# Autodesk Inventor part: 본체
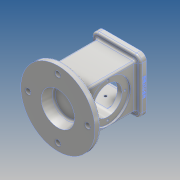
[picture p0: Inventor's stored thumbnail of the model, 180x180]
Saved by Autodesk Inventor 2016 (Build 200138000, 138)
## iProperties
Created: 2018-10
Part Number: 본체
Material: 알루미늄 6061
Document SubType Name: Modeling
Designer: Administrator
Density: 2.7 g/cm^3
Appearance: 알루미늄 - 평지
Mass: 1090.69 g
Surface Area: 720.185 cm^2
Volume: 403.96 cm^3
Author: Administrator
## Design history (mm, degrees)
sketch "스케치1"
  geometry: C1 r 62.5 at (0, 0); 1 further point
  constraints: 1 centre point, 1 coincident
  dimensions: "d0" = 125 diameter of C1
extrude "돌출1" new body sketch "스케치1" distance "d1" = 10; taper "d2" = 0 deg
sketch "스케치2"
  geometry: L1 (33, 37)-(-33, 37); L2 (-33, 37)-(-33, -37); L3 (-33, -37)-(33, -37); L4 (33, -37)-(33, 37); L5 (33, 37)-(-33, -37); L6 (-33, 37)-(33, -37); C1 r 62.5 at (0, 0) reference
  constraints: 12 end point, 2 midpoint, 2 parallel, 1 horizontal, 1 perpendicular
  dimensions: "d3" = 66 distance of L3.end L2.end; "d4" = 74 distance of L2.end L1.end
extrude "돌출2" join sketch "스케치2" distance "d5" = 88; taper "d6" = 0 deg
sketch "스케치3"
  geometry: L1 (41, 46)-(-41, 46); L2 (-41, 46)-(-41, -46); L3 (-41, -46)-(41, -46); L4 (41, -46)-(41, 46); L5 (41, 46)-(-41, -46); L6 (-41, 46)-(41, -46); 1 further point
  constraints: 12 end point, 2 midpoint, 2 parallel, 1 horizontal, 1 perpendicular
  dimensions: "d7" = 82 distance of L3.end L2.end; "d8" = 92 distance of L2.end L1.end
extrude "돌출3" join sketch "스케치3" distance "d9" = 10; taper "d10" = 0 deg
fillet "모깎기1" dims "d11" = 3
fillet "모깎기2" dims "d12" = 10
sketch "스케치4"
  geometry: C1 r 59.5 at (0, 0) reference; 4 further points
  constraints: 2 horizontal alignment, 2 vertical alignment
  dimensions: "d13" = 100 distance of point (0, 50) point (0, -50); "d14" = 100 distance of point (-50, 0) point (50, 0); "d15" = 50 horizontal distance of point (-50, 0) point (0, -50); "d16" = 50 horizontal distance of point (0, 50) point (50, 0)
hole "구멍1" sketch "스케치4" at (0, -50), (0, 50), (-50, 0), (50, 0) diameter "d17" = 9; stored, may be unused: countersink angle "d21" = 90 deg, drill point angle "d23" = 0 deg; dims "d18" = 6, "d19" = 4, "d20" = 2, "d22" = 8
sketch "스케치6"
  geometry: L1 (-33, 13)-(-33, 95) reference; L2 (-33, 54)-(33, 54); L3 (33, 95)-(33, 13) reference; L4 (-33, 54)-(-33, 89); L5 (-33, 89)-(-30, 89); L6 (-30, 89)-(-30, 78); L7 (-30, 78)-(30, 78); L8 (30, 78)-(30, 89); L9 (30, 89)-(33, 89); L10 (33, 89)-(33, 54); 1 further point
  constraints: 16 end point, 4 point on line, 3 perpendicular, 2 collinear, 2 midpoint, 1 horizontal
  dimensions: "d24" = 70 diameter of L5 L2; "d25" = 48 diameter of L7 L2; "d26" = 3 distance between parallel lines of L1 L6
revolve "회전1" sketch "스케치6" stored, may be unused: angle "d27" = 90 deg
sketch "스케치7"
  geometry: C1 r 35 at (0, 0) reference; C2 r 24 at (0, 0) reference; A1 r 29 centre (0, 0) between (0, 29) and (-29, 0); 3 further points
  constraints: 4 point on circle, 2 horizontal alignment, 2 vertical alignment, 1 centre point, 1 coincident
  dimensions: "d28" = 58 diameter of A1
hole "구멍2" sketch "스케치7" at (0, 29), (-29, 0), (0, -29), (29, 0) diameter "d29" = 3.242; stored, may be unused: countersink angle "d33" = 90 deg, drill point angle "d35" = 118 deg; dims "d30" = 4, "d31" = 4, "d32" = 2, "d34" = 6
sketch "스케치8"
  geometry: L1 (-26, -26)-(26, -26); L2 (26, -26)-(26, 26); L3 (26, 26)-(-26, 26); L4 (-26, 26)-(-26, -26); L5 (-26, -26)-(26, 26); L6 (26, -26)-(-26, 26); 1 further point
  constraints: 12 end point, 2 midpoint, 2 parallel, 1 horizontal, 1 perpendicular
  dimensions: "d36" = 52 distance of L3.end L2.end; "d37" = 52 distance of L2.end L1.end
extrude "돌출4" cut sketch "스케치8" distance "d38" = 8; taper "d39" = 0 deg
sketch "스케치9"
  geometry: L1 (-22, -22)-(22, -22); L2 (22, -22)-(22, 22); L3 (22, 22)-(-22, 22); L4 (-22, 22)-(-22, -22); L5 (-22, -22)-(22, 22); L6 (22, -22)-(-22, 22); 1 further point
  constraints: 12 end point, 2 midpoint, 2 parallel, 1 horizontal, 1 perpendicular
  dimensions: "d40" = 44 distance of L3.end L2.end; "d41" = 44 distance of L2.end L1.end
extrude "돌출5" cut sketch "스케치9" distance "d42" = 74; taper "d43" = 0 deg
chamfer "모따기1" distance "d44" = 1; stored, may be unused: second distance "d45" = 2, angle "d46" = 45 deg
fillet "모깎기3" dims "d47" = 3
sketch "스케치10"
  geometry: A1 r 10 centre (31, 36) between (41, 36) and (31, 46) reference; A2 r 10 centre (-31, 36) between (-31, 46) and (-41, 36) reference; A3 r 10 centre (-31, -36) between (-41, -36) and (-31, -46) reference; A4 r 10 centre (31, -36) between (31, -46) and (41, -36) reference; 5 further points
  constraints: 4 coincident
hole "구멍3" sketch "스케치10" at (-31, -36), (31, -36), (31, 36), (-31, 36) diameter "d48" = 3.242; stored, may be unused: countersink angle "d52" = 90 deg, drill point angle "d54" = 118 deg; dims "d49" = 4, "d50" = 4, "d51" = 2, "d53" = 6
sketch "스케치11"
  geometry: L1 (-72, 7)-(0, 7) reference; L2 (-82, 7)-(-82, 0) reference; 2 further points
  constraints: 1 other
  dimensions: "d55" = 46 distance from line of L2 point (-36, 3); "d57" = 4 distance from line of L1 point (-36, 3)
feature "엠보싱1" sketch "스케치11" dims "d58" = 0.5, "d59" = 0
sketch "스케치12"
  geometry: 3 further points
  constraints: 2 vertical alignment
  dimensions: "d60" = 37 distance of point (30, -13) point (30, 24); "d61" = 43 distance of point (30, 67) point (30, 24)
hole "구멍4" sketch "스케치12" at (30, 67), (30, 24) diameter "d62" = 4.134; stored, may be unused: countersink angle "d66" = 90 deg, drill point angle "d68" = 0 deg; dims "d63" = 10, "d64" = 4, "d65" = 2, "d67" = 15
sketch "스케치13"
  geometry: L1 (0, 0)-(26, 0); L2 (26, 19)-(26, -19) reference; L3 (0, 0)-(0, 28); L4 (0, 62.5)-(0, -62.5) reference; L5 (0, 28)-(15.521, 25.263); L6 (18, 22.309)-(18, 0); A1 r 3 centre (15, 22.309) between (18, 22.309) and (15.521, 25.263)
  constraints: 8 end point, 2 point on circle, 2 point on line, 2 tangent, 1 centre point, 1 midpoint, 1 perpendicular
  dimensions: "d69" = 56 diameter of L3.end L1; "d70" = 80 deg angle of L3 L5; "d71" = 18 distance between parallel lines of L3 L6; "d72" = 3 radius of A1
revolve "회전2" sketch "스케치13" stored, may be unused: angle "d73" = 90 deg
node "솔리드1"
mirror "대칭1"
